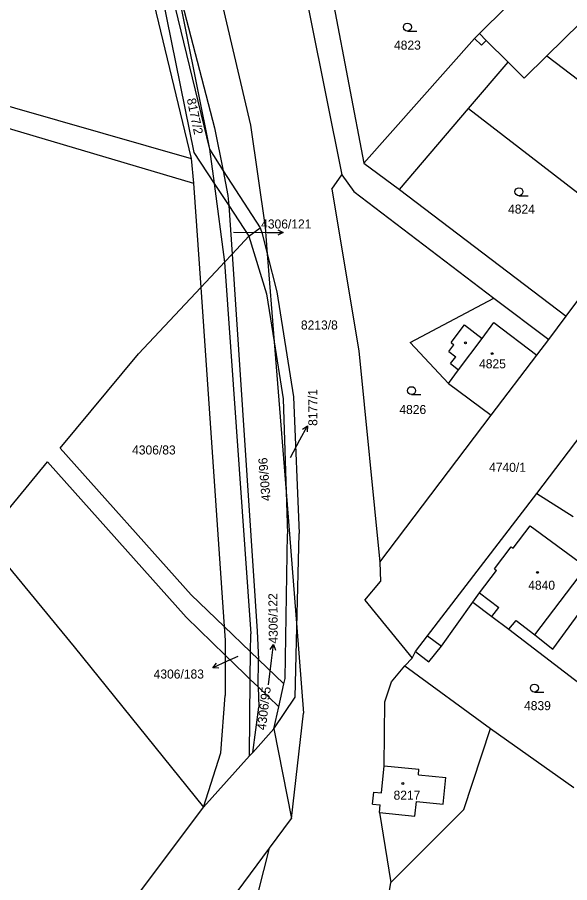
# Model space of a CAD drawing. Extents: x -717507 to -715515, y -957700 to -954941.
# Drawn here: x -716735.3 to -716631.1, y -956492.7 to -956329.6 of the extents above; entities that cross this region are included whole.
import ezdxf

# ---------------------------------------------------------------- set-up
doc = ezdxf.new("R2010")
doc.units = 0
for name, color, linetype in [('Hranice parcel', 7, 'Continuous'), ('Parcelní čísla', 7, 'Continuous'), ('Pop  PČ popisy', 7, 'Continuous'), ('Vnitřní kresba', 7, 'Continuous'), ('Značky budov', 7, 'Continuous'), ('Značky kultur', 7, 'Continuous')]:
    doc.layers.add(name, color=color, linetype=linetype)

msp = doc.modelspace()

# ---------------------------------------------------------------- linework, layer by layer
at = {"layer": 'Hranice parcel'}
for points in [[(-716732.53, -956231.41), (-716702.47, -956356.16)], [(-716686, -956299.79), (-716674.07, -956359.28)], [(-716709.35, -956311.97), (-716699, -956354.43)], [(-716708.81, -956321.23), (-716701.97, -956355.02)], [(-716705.82, -956320.64), (-716699, -956354.43)], [(-716648.14, -956332.64), (-716638.07, -956322.6)], [(-716675.59, -956327.4), (-716669.91, -956357.08)], [(-716649.05, -956333.55), (-716648.14, -956332.64)], [(-716649.05, -956333.55), (-716647.76, -956334.82)], [(-716647.76, -956334.82), (-716646.86, -956333.91)], [(-716646.86, -956333.91), (-716642.73, -956338.02)], [(-716639.68, -956341.06), (-716635.41, -956336.85)], [(-716635.41, -956336.85), (-716609.69, -956356.34)], [(-716650.18, -956346.74), (-716642.73, -956338.02)], [(-716642.73, -956338.02), (-716639.68, -956341.06)], [(-716663.19, -956361.99), (-716650.18, -956346.74)], [(-716650.18, -956346.74), (-716619.94, -956370.06)], [(-716699, -956354.43), (-716698.14, -956360.86)], [(-716699, -956354.43), (-716696.48, -956358.48)], [(-716702.47, -956356.16), (-716702.03, -956360.84)], [(-716701.97, -956355.02), (-716698.14, -956360.86)], [(-716669.91, -956357.08), (-716663.19, -956361.99)], [(-716696.48, -956358.48), (-716689.45, -956369.23)], [(-716675.96, -956361.96), (-716674.07, -956359.28)], [(-716674.07, -956359.28), (-716671.82, -956362.39)], [(-716702.03, -956360.84), (-716700.67, -956380.49)], [(-716698.14, -956360.86), (-716695.41, -956365.04)], [(-716698.14, -956360.86), (-716696.17, -956375.7)], [(-716675.96, -956361.96), (-716670.88, -956392.4)], [(-716671.82, -956362.39), (-716645.42, -956382.48)], [(-716663.19, -956361.99), (-716631.77, -956385.88)], [(-716695.41, -956365.04), (-716691.62, -956370.84)], [(-716689.45, -956369.23), (-716689.1, -956370.34)], [(-716694.77, -956374.21), (-716691.62, -956370.84)], [(-716691.62, -956370.84), (-716688.26, -956381.7)], [(-716689.1, -956370.34), (-716688.14, -956374.13)], [(-716631.77, -956385.88), (-716619.94, -956370.06)], [(-716696.17, -956375.7), (-716694.77, -956374.21)], [(-716688.14, -956374.13), (-716686.31, -956381.32)], [(-716696.97, -956376.56), (-716696.17, -956375.7)], [(-716696.17, -956375.7), (-716691.23, -956445.77)], [(-716700.67, -956380.49), (-716696.97, -956376.56)], [(-716712.43, -956393.01), (-716700.67, -956380.49)], [(-716688.26, -956381.7), (-716686.83, -956390.71)], [(-716686.31, -956381.32), (-716683.2, -956401.1)], [(-716661.17, -956390.86), (-716645.42, -956382.48)], [(-716645.42, -956382.48), (-716635.03, -956390.3)], [(-716635.03, -956390.3), (-716631.77, -956385.88)], [(-716637.28, -956393.24), (-716635.03, -956390.3)], [(-716686.83, -956390.71), (-716685.13, -956401.48)], [(-716661.17, -956390.86), (-716653.98, -956398.6)], [(-716727.16, -956410.74), (-716712.43, -956393.01)], [(-716670.88, -956392.4), (-716666.94, -956432.28)], [(-716645.91, -956404.54), (-716637.28, -956393.24)], [(-716653.98, -956398.6), (-716645.91, -956404.54)], [(-716685.13, -956401.48), (-716684.59, -956418.99)], [(-716683.2, -956401.1), (-716682.15, -956426.83)], [(-716637.28, -956419.31), (-716623.99, -956401.79)], [(-716666.94, -956432.28), (-716645.91, -956404.54)], [(-716727.16, -956410.74), (-716702.51, -956438.39)], [(-716741.45, -956427.73), (-716729.56, -956413.32)], [(-716729.56, -956413.32), (-716703.4, -956442.63)], [(-716684.59, -956418.99), (-716684.35, -956426.91)], [(-716657.9, -956446.11), (-716637.28, -956419.31)], [(-716637.28, -956419.31), (-716630.45, -956423.66)], [(-716634.28, -956448.68), (-716613.3, -956419.93)], [(-716684.77, -956454.21), (-716684.35, -956426.91)], [(-716682.57, -956444.54), (-716682.15, -956426.83)], [(-716666.94, -956432.28), (-716666.79, -956435.87)], [(-716637.69, -956445.93), (-716628.16, -956433.36)], [(-716669.73, -956439.43), (-716666.79, -956435.87)], [(-716702.51, -956438.39), (-716696.25, -956444.39)], [(-716669.73, -956439.43), (-716660.81, -956450.35)], [(-716655.31, -956448.11), (-716649.35, -956439.79)], [(-716649.35, -956439.79), (-716645.77, -956442.48)], [(-716703.4, -956442.63), (-716696.07, -956449.76)], [(-716645.77, -956442.48), (-716642.56, -956444.9)], [(-716696.25, -956444.39), (-716696.07, -956446.95)], [(-716696.25, -956444.39), (-716691.27, -956449.16)], [(-716642.56, -956444.9), (-716641.22, -956443.22)], [(-716641.22, -956443.22), (-716637.69, -956445.93)], [(-716691.27, -956449.16), (-716691.23, -956445.77)], [(-716682.88, -956457.7), (-716682.57, -956444.54)], [(-716660.19, -956449.11), (-716657.9, -956446.11)], [(-716657.9, -956446.11), (-716655.31, -956448.11)], [(-716642.56, -956444.9), (-716619.72, -956462.4)], [(-716637.69, -956445.93), (-716634.28, -956448.68)], [(-716696.07, -956446.95), (-716696.07, -956449.76)], [(-716691.33, -956454.37), (-716691.27, -956449.16)], [(-716691.27, -956449.16), (-716689.78, -956450.58)], [(-716660.81, -956450.35), (-716660.19, -956449.11)], [(-716696.07, -956449.76), (-716692.39, -956453.34)], [(-716689.78, -956450.58), (-716684.99, -956455.18)], [(-716662.19, -956451.8), (-716660.81, -956450.35)], [(-716664.72, -956454.78), (-716662.19, -956451.8)], [(-716662.19, -956451.8), (-716646.06, -956463.62)], [(-716692.39, -956453.34), (-716691.33, -956454.37)], [(-716684.99, -956455.18), (-716684.77, -956454.21)], [(-716691.49, -956468.76), (-716691.33, -956454.37)], [(-716691.33, -956454.37), (-716689.84, -956455.78)], [(-716689.84, -956455.78), (-716685.98, -956459.53)], [(-716685.98, -956459.53), (-716684.99, -956455.18)], [(-716665.94, -956458.56), (-716664.72, -956454.78)], [(-716686.92, -956463.64), (-716682.88, -956457.7)], [(-716666.09, -956470.63), (-716665.94, -956458.56)], [(-716686.92, -956463.64), (-716685.98, -956459.53)], [(-716690.86, -956468.13), (-716686.92, -956463.64)], [(-716686.92, -956463.64), (-716683.56, -956480.59)], [(-716651.04, -956478.87), (-716646.06, -956463.62)], [(-716646.06, -956463.62), (-716630.35, -956474.72)], [(-716700.15, -956478.45), (-716691.49, -956468.76)], [(-716691.49, -956468.76), (-716690.86, -956468.13)], [(-716666.61, -956475.75), (-716666.09, -956470.63)], [(-716668.29, -956477.84), (-716668.06, -956475.6)], [(-716668.06, -956475.6), (-716666.61, -956475.75)], [(-716744.64, -956537.69), (-716700.15, -956478.45)], [(-716668.29, -956477.84), (-716666.84, -956477.98)], [(-716666.98, -956479.45), (-716666.84, -956477.98)], [(-716666.98, -956479.45), (-716664.83, -956492.6)], [(-716664.83, -956492.6), (-716651.04, -956478.87)], [(-716687.74, -956486.16), (-716683.56, -956480.59)], [(-716768.39, -956595.03), (-716687.74, -956486.16)], [(-716697.15, -956523.28), (-716687.74, -956486.16)], [(-716667.57, -956509.57), (-716664.83, -956492.6)]]:
    msp.add_lwpolyline(points, dxfattribs=at)
at = {"layer": 'Pop  PČ popisy'}
for points in [[(-716694.53, -956370.04), (-716688.16, -956370.1)], [(-716688.16, -956370.1), (-716685.16, -956370.13)], [(-716686.15, -956369.62), (-716685.16, -956370.13), (-716686.17, -956370.62)], [(-716681.97, -956409.19), (-716680.54, -956406.55)], [(-716681.46, -956407.19), (-716680.54, -956406.55), (-716680.58, -956407.67)], [(-716683.76, -956412.51), (-716681.97, -956409.19)], [(-716687.56, -956448.72), (-716686.93, -956447.79), (-716686.57, -956448.85)], [(-716687.32, -956450.77), (-716686.93, -956447.79)], [(-716695.67, -956450.93), (-716698.4, -956452.18)], [(-716693.7, -956450.02), (-716695.67, -956450.93)], [(-716687.92, -956455.38), (-716687.32, -956450.77)], [(-716697.28, -956452.22), (-716698.4, -956452.18), (-716697.7, -956451.31)]]:
    msp.add_lwpolyline(points, dxfattribs=at)
at = {"layer": 'Vnitřní kresba'}
for points in [[(-716721.95, -956219.11), (-716691.32, -956349.9)], [(-716705.82, -956320.64), (-716698.11, -956350.39)], [(-716635.41, -956336.85), (-716619.79, -956321.43)], [(-716669.91, -956357.08), (-716649.05, -956333.55)], [(-716648.14, -956332.64), (-716646.86, -956333.91)], [(-716744.43, -956344.18), (-716702.47, -956356.16)], [(-716745.54, -956347.92), (-716702.03, -956360.84)], [(-716691.32, -956349.9), (-716688.54, -956369.12)], [(-716698.11, -956350.39), (-716696.48, -956358.48)], [(-716696.48, -956358.48), (-716695.54, -956363.16)], [(-716695.54, -956363.16), (-716695.41, -956365.04)], [(-716695.41, -956365.04), (-716694.77, -956374.21)], [(-716691.62, -956370.84), (-716689.45, -956369.23)], [(-716688.54, -956369.12), (-716688.14, -956374.13)], [(-716694.77, -956374.21), (-716690.02, -956445.23)], [(-716688.14, -956374.13), (-716686.83, -956390.71)], [(-716700.67, -956380.49), (-716696.25, -956444.39)], [(-716647.64, -956390.08), (-716645.4, -956387.07)], [(-716645.4, -956387.07), (-716637.28, -956393.24)], [(-716653.48, -956390.88), (-716650.92, -956387.53)], [(-716650.92, -956387.53), (-716647.64, -956390.08)], [(-716652.06, -956396.02), (-716647.64, -956390.08)], [(-716686.83, -956390.71), (-716684.59, -956418.99)], [(-716653.89, -956392.58), (-716652.93, -956391.29)], [(-716653.48, -956390.88), (-716652.93, -956391.29)], [(-716653.89, -956392.58), (-716652.56, -956393.58)], [(-716653.56, -956394.83), (-716652.56, -956393.58)], [(-716653.56, -956394.83), (-716652.06, -956396.02)], [(-716653.98, -956398.6), (-716652.06, -956396.02)], [(-716684.59, -956418.99), (-716682.57, -956444.54)], [(-716641.77, -956429.64), (-716638.56, -956425.39)], [(-716638.56, -956425.39), (-716628.39, -956432.9)], [(-716741.45, -956427.73), (-716724.57, -956448.23)], [(-716645.3, -956433.49), (-716642.17, -956429.34)], [(-716642.17, -956429.34), (-716641.77, -956429.64)], [(-716648.09, -956438.04), (-716644.89, -956433.8)], [(-716645.3, -956433.49), (-716644.89, -956433.8)], [(-716649.35, -956439.79), (-716648.09, -956438.04)], [(-716648.09, -956438.04), (-716644.45, -956440.79)], [(-716645.77, -956442.48), (-716644.45, -956440.79)], [(-716690.02, -956445.23), (-716689.78, -956450.58)], [(-716682.57, -956444.54), (-716681.29, -956460.69)], [(-716724.57, -956448.23), (-716700.15, -956478.45)], [(-716660.19, -956449.11), (-716657.64, -956451.05)], [(-716657.64, -956451.05), (-716655.31, -956448.11)], [(-716696.07, -956449.76), (-716696.06, -956457.4)], [(-716689.84, -956455.78), (-716689.78, -956450.58)], [(-716689.84, -956455.78), (-716689.72, -956459.61)], [(-716696.9, -956468.21), (-716696.06, -956457.4)], [(-716690.86, -956468.13), (-716689.72, -956459.61)], [(-716683.56, -956480.59), (-716681.29, -956460.69)], [(-716700.15, -956478.45), (-716696.9, -956468.21)], [(-716666.09, -956470.63), (-716659.54, -956471.3)], [(-716659.59, -956472.35), (-716659.54, -956471.3)], [(-716659.59, -956472.35), (-716654.47, -956472.87)], [(-716654.94, -956477.88), (-716654.47, -956472.87)], [(-716660.3, -956480.13), (-716660.02, -956477.37)], [(-716660.02, -956477.37), (-716654.94, -956477.88)], [(-716666.98, -956479.45), (-716660.3, -956480.13)]]:
    msp.add_lwpolyline(points, dxfattribs=at)
at = {"layer": 'Značky budov'}
for centre in [(-716650.78, -956390.93), (-716645.73, -956392.95), (-716637.18, -956434.18), (-716662.58, -956473.96)]:
    msp.add_circle(centre, 0.175, dxfattribs=at)
at = {"layer": 'Značky kultur'}
for points in [[(-716661.71, -956332.17), (-716659.96, -956332.17)], [(-716640.68, -956363.19), (-716638.93, -956363.19)], [(-716660.93, -956400.68), (-716659.18, -956400.68)], [(-716637.76, -956456.73), (-716636.01, -956456.73)]]:
    msp.add_lwpolyline(points, dxfattribs=at)
for centre in [(-716661.71, -956331.42), (-716640.68, -956362.44), (-716660.93, -956399.93), (-716637.76, -956455.98)]:
    msp.add_circle(centre, 0.75, dxfattribs=at)

# ---------------------------------------------------------------- texts
at = {"layer": 'Parcelní čísla'}
for s, p in [('4823', (-716664.24, -956335.66)), ('4824', (-716642.73, -956366.56)), ('4306/121', (-716689.29, -956369.37)), ('8213/8', (-716681.79, -956388.41)), ('4825', (-716648.2, -956395.72)), ('4826', (-716663.23, -956404.34)), ('4306/83', (-716713.62, -956411.96)), ('4740/1', (-716646.31, -956415.23)), ('4840', (-716638.93, -956437.45)), ('4306/183', (-716709.56, -956454.19)), ('4839', (-716639.72, -956460.15)), ('8217', (-716664.32, -956477.02))]:
    msp.add_text(s, height=1.7, dxfattribs=at).set_placement(p)
for s, rotation, p in [('8177/2', 282.0022, (-716703.33, -956344.99)), ('8177/1', 90.3007, (-716678.69, -956406.57)), ('4306/96', 94.6008, (-716687.49, -956420.68)), ('4306/122', 90.6007, (-716686.14, -956447.59)), ('4306/95', 83.2007, (-716688.43, -956463.99))]:
    msp.add_text(s, height=1.7, rotation=rotation, dxfattribs=at).set_placement(p)

doc.saveas('drawing.dxf')
